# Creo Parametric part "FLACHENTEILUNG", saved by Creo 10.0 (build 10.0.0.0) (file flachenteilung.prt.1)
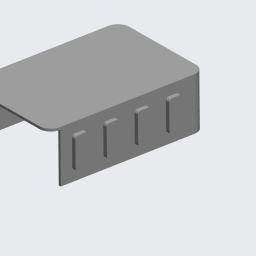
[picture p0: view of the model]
Materials in the file: S235JRG2

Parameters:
  BENENNUNG = "XXX"
  DATUM = "XX.XX.XX"
  ERSTELLER = "ARINDA"
  TEILETYP = "Fertigungsteil"
  PTC_MASTER_MATERIAL = "S235JRG2"
  SELECT_EN_NAME = "S235JRG2"
  SELECT_DIN_NAME = "RSt37-2"
  SELECT_DIN_NUMBER = "1.0038"
  SELECT_ASTM_NAME = "A 283 M Grade 2"
  MATERIAL_GROUP = "ME_ST_Baustahl"
  STANDARD_EN_DELIVERYSPEC = "DIN EN 10025"
  STANDARD_DIN_DELIVERYSPEC = "DIN 17100"

Other parameters: MASSE

Created from: ARINDA-STARTTEIL.PRT

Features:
  1. coordinate system "CS0"
  2. datum plane "DTM1", "T_RECHTS_Y-Z"
  3. datum plane "DTM2", "T_OBEN_X-Z"
  4. datum plane "DTM3", "T_VORNE_X-Y"
  5. datum axis "T_X-ACHSE"
  6. datum axis "A_1"
  7. datum axis "A_2"
  8. extrusion "Profil 1"
  9. round "Rundung 1"
  10. pattern "Muster 1"
  11. extrusion "Profil 2"
  12. extrusion "Profil 2 [2]"
  13. extrusion "Profil 2 [3]"
  14. extrusion "Profil 2 [4]"
  15. shell "Schale 1"
  16. feature "Fläche Teilen 1"
  17. feature "Flächen Vereinigen 1"
  18. feature "Flächen Vereinigen 2"

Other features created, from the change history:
  extrusion "Profil 2 [2]"
  feature "Flächen Vereinigen 1"
  feature "Versatz 1"
  patch "Verbundvolumen 1"

Other named items: T_BASIC, T_Y-ACHSE, T_Z-ACHSE

Layers: 00_STD-ACHSEN, 00_STD-EBENEN, 00_STD-KOORDSYS, FLAECHEN, SAMMELFLÄCHEN, VOLUMENGEOMETRIE

Surfaces: 61 plane, 38 cylinder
